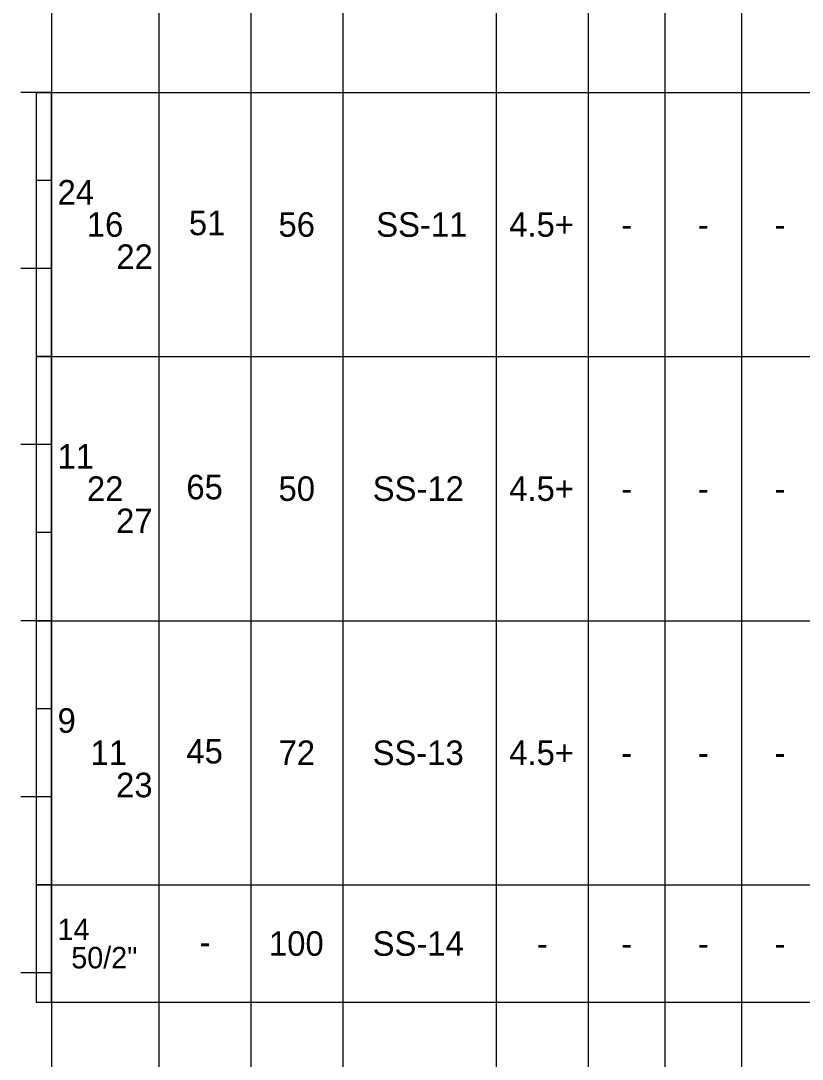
# Model space of a CAD drawing. Extents: x -0.01 to 0.83, y -0.63 to 1.27.
# Drawn here: x 0.4042 to 0.6165, y 0.1679 to 0.45 of the extents above; entities that cross this region are included whole.
import ezdxf

# ---------------------------------------------------------------- set-up
doc = ezdxf.new("R2010")
doc.units = 0

msp = doc.modelspace()

# ---------------------------------------------------------------- linework, layer by layer
for points in [[(0.4125, 1.22083), (0.4125, -0.62183)], [(0.4125, 1.22083), (0.4125, -0.62183)], [(0.44167, 1.22083), (0.44167, -0.62183)], [(0.46667, 1.22083), (0.46667, -0.62183)], [(0.49167, 1.22083), (0.49167, -0.62183)], [(0.53333, 1.22083), (0.53333, -0.62183)], [(0.55833, 1.22083), (0.55833, -0.62183)], [(0.57917, 1.20833), (0.57917, -0.62183)], [(0.6, 1.20833), (0.6, -0.62183)], [(0.4125, 0.4305), (0.40417, 0.4305)], [(0.40833, 0.4305), (0.40833, 0.35875)], [(0.40833, 0.4305), (0.4125, 0.4305)], [(0.4125, 0.4305), (0.40833, 0.4305)], [(0.4125, 0.4305), (0.44167, 0.4305)], [(0.44167, 0.4305), (0.46667, 0.4305)], [(0.46667, 0.4305), (0.49167, 0.4305)], [(0.49167, 0.4305), (0.53333, 0.4305)], [(0.53333, 0.4305), (0.55833, 0.4305)], [(0.55833, 0.4305), (0.57917, 0.4305)], [(0.57917, 0.4305), (0.6, 0.4305)], [(0.6, 0.4305), (0.62083, 0.4305)], [(0.4125, 0.40658), (0.40833, 0.40658)], [(0.4125, 0.38267), (0.40417, 0.38267)], [(0.4125, 0.38267), (0.40833, 0.38267)], [(0.40833, 0.35875), (0.4125, 0.35875)], [(0.40833, 0.35875), (0.40833, 0.287)], [(0.40833, 0.35875), (0.4125, 0.35875)], [(0.4125, 0.35875), (0.40833, 0.35875)], [(0.4125, 0.35875), (0.44167, 0.35875)], [(0.44167, 0.35875), (0.46667, 0.35875)], [(0.46667, 0.35875), (0.49167, 0.35875)], [(0.49167, 0.35875), (0.53333, 0.35875)], [(0.53333, 0.35875), (0.55833, 0.35875)], [(0.55833, 0.35875), (0.57917, 0.35875)], [(0.57917, 0.35875), (0.6, 0.35875)], [(0.6, 0.35875), (0.62083, 0.35875)], [(0.4125, 0.33483), (0.40417, 0.33483)], [(0.4125, 0.33483), (0.40833, 0.33483)], [(0.4125, 0.31092), (0.40833, 0.31092)], [(0.4125, 0.287), (0.40417, 0.287)], [(0.40833, 0.287), (0.4125, 0.287)], [(0.40833, 0.287), (0.40833, 0.21525)], [(0.40833, 0.287), (0.4125, 0.287)], [(0.4125, 0.287), (0.40833, 0.287)], [(0.4125, 0.287), (0.44167, 0.287)], [(0.44167, 0.287), (0.46667, 0.287)], [(0.46667, 0.287), (0.49167, 0.287)], [(0.49167, 0.287), (0.53333, 0.287)], [(0.53333, 0.287), (0.55833, 0.287)], [(0.55833, 0.287), (0.57917, 0.287)], [(0.57917, 0.287), (0.6, 0.287)], [(0.6, 0.287), (0.62083, 0.287)], [(0.4125, 0.26308), (0.40833, 0.26308)], [(0.4125, 0.23917), (0.40417, 0.23917)], [(0.4125, 0.23917), (0.40833, 0.23917)], [(0.40833, 0.21525), (0.4125, 0.21525)], [(0.40833, 0.21525), (0.40833, 0.18336)], [(0.40833, 0.21525), (0.4125, 0.21525)], [(0.4125, 0.21525), (0.40833, 0.21525)], [(0.4125, 0.21525), (0.44167, 0.21525)], [(0.44167, 0.21525), (0.46667, 0.21525)], [(0.46667, 0.21525), (0.49167, 0.21525)], [(0.49167, 0.21525), (0.53333, 0.21525)], [(0.53333, 0.21525), (0.55833, 0.21525)], [(0.55833, 0.21525), (0.57917, 0.21525)], [(0.57917, 0.21525), (0.6, 0.21525)], [(0.6, 0.21525), (0.62083, 0.21525)], [(0.4125, 0.19133), (0.40417, 0.19133)], [(0.4125, 0.19133), (0.40833, 0.19133)], [(0.40833, 0.18336), (0.4125, 0.18336)], [(0.4125, 0.18336), (0.44167, 0.18336)], [(0.44167, 0.18336), (0.46667, 0.18336)], [(0.46667, 0.18336), (0.49167, 0.18336)], [(0.49167, 0.18336), (0.53333, 0.18336)], [(0.53333, 0.18336), (0.55833, 0.18336)], [(0.55833, 0.18336), (0.57917, 0.18336)], [(0.57917, 0.18336), (0.6, 0.18336)], [(0.6, 0.18336), (0.62083, 0.18336)]]:
    msp.add_lwpolyline(points)
for points in [[(0.40833, 0.35875), (0.4125, 0.35875), (0.4125, 0.4305), (0.40833, 0.4305)], [(0.40833, 0.287), (0.4125, 0.287), (0.4125, 0.35875), (0.40833, 0.35875)], [(0.40833, 0.21525), (0.4125, 0.21525), (0.4125, 0.287), (0.40833, 0.287)], [(0.40833, 0.18336), (0.4125, 0.18336), (0.4125, 0.21525), (0.40833, 0.21525)]]:
    msp.add_lwpolyline(points, close=True)

# ---------------------------------------------------------------- texts
for s, height, p in [('24', 0.006667, (0.41417, 0.40004)), ('16', 0.006667, (0.42212, 0.39129)), ('51', 0.006667, (0.44984, 0.39171)), ('56', 0.006667, (0.4742, 0.39129)), ('SS-11', 0.006667, (0.50076, 0.39129)), ('4.5+', 0.006667, (0.5369, 0.39129)), ('-', 0.00667, (0.56734, 0.39129)), ('-', 0.00667, (0.58818, 0.39129)), ('-', 0.00667, (0.60901, 0.39129)), ('22', 0.006667, (0.43014, 0.38254)), ('11', 0.006667, (0.41417, 0.32829)), ('22', 0.006667, (0.42215, 0.31954)), ('65', 0.006667, (0.44917, 0.31996)), ('50', 0.006667, (0.47421, 0.31954)), ('SS-12', 0.006667, (0.4998, 0.31954)), ('4.5+', 0.006667, (0.5369, 0.31954)), ('-', 0.00667, (0.56734, 0.31954)), ('-', 0.00667, (0.58818, 0.31954)), ('-', 0.00667, (0.60901, 0.31954)), ('27', 0.006667, (0.43007, 0.31079)), ('9', 0.00667, (0.41417, 0.25654)), ('11', 0.006667, (0.42311, 0.24779)), ('45', 0.006667, (0.44917, 0.24821)), ('72', 0.006667, (0.47423, 0.24779)), ('SS-13', 0.006667, (0.49977, 0.24779)), ('4.5+', 0.006667, (0.5369, 0.24779)), ('-', 0.00667, (0.56734, 0.24779)), ('-', 0.00667, (0.58818, 0.24779)), ('-', 0.00667, (0.60901, 0.24779)), ('23', 0.006667, (0.43007, 0.23904)), ('14', 0.005833, (0.41417, 0.20022)), ('100', 0.006667, (0.47162, 0.19597)), ('SS-14', 0.006667, (0.49978, 0.19597)), ('50/2"', 0.005833, (0.4179, 0.19256)), ('-', 0.00667, (0.45276, 0.19639)), ('-', 0.00667, (0.54443, 0.19597)), ('-', 0.00667, (0.56734, 0.19597)), ('-', 0.00667, (0.58818, 0.19597)), ('-', 0.00667, (0.60901, 0.19597))]:
    msp.add_text(s, height=height).set_placement(p)

doc.saveas('drawing.dxf')
